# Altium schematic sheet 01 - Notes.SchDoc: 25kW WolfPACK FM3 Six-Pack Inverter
size 431 x 279 mm; Date: 09/2024; DocumentNumber: CRD25DA12N-FMC; Revision: 2.0; SheetNumber: 1; SheetTotal: 9; SheetSize: B
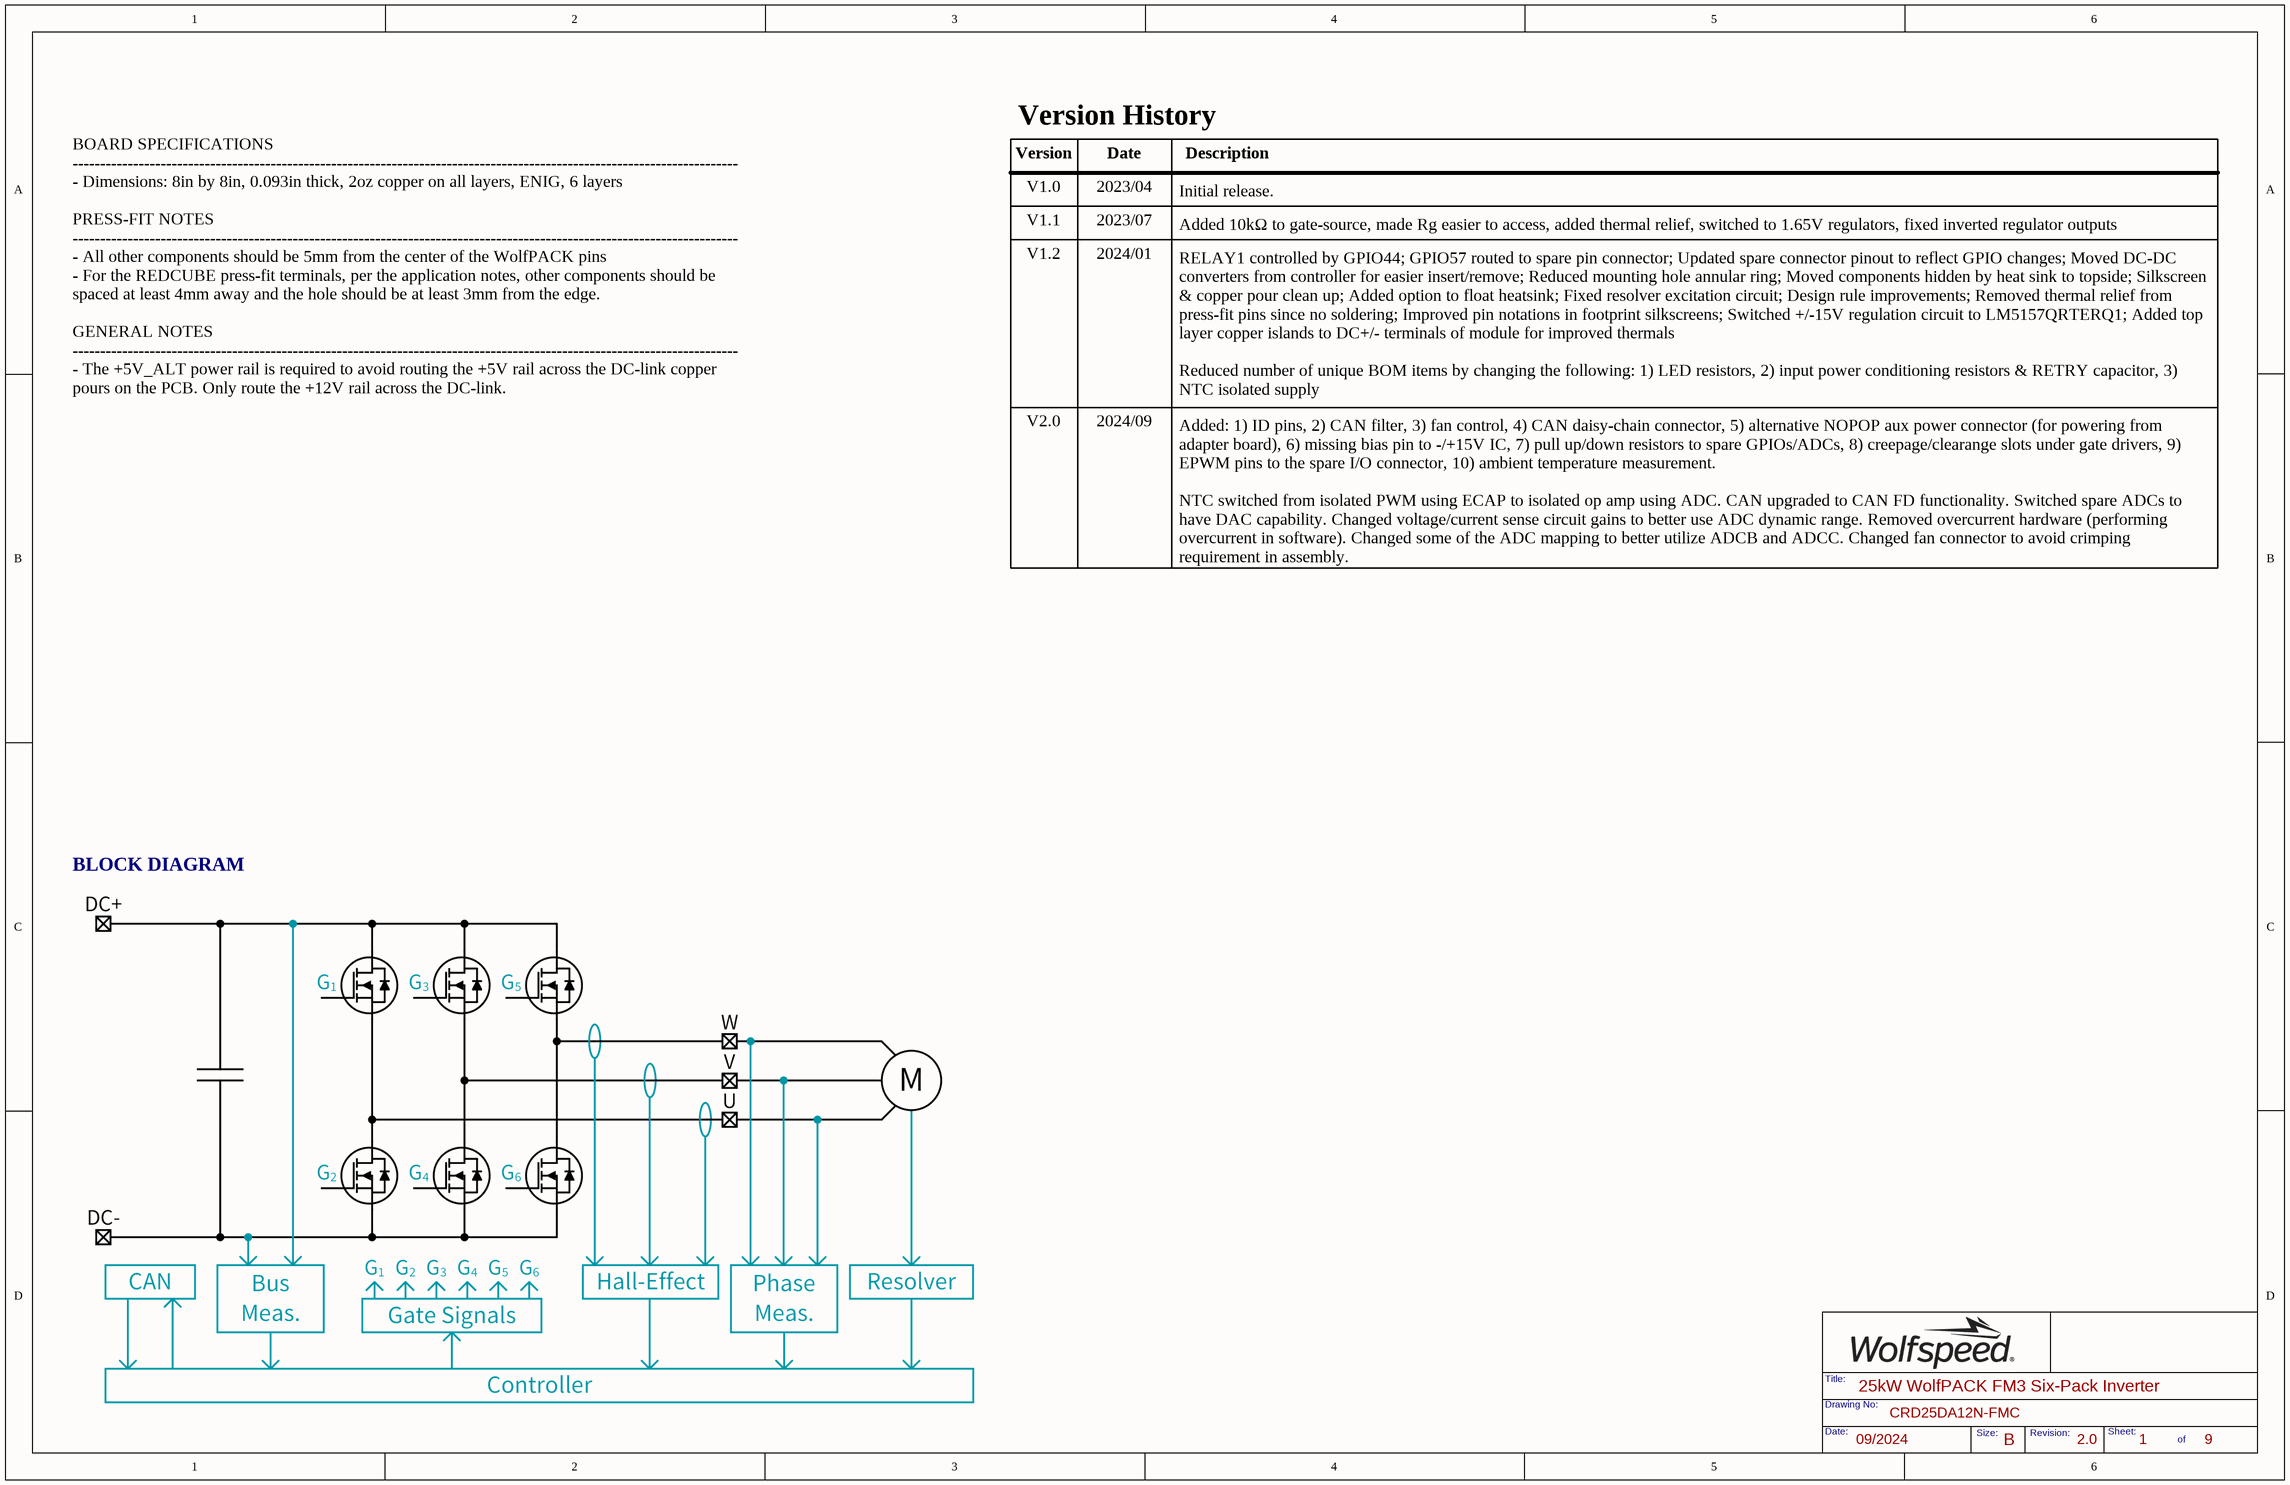
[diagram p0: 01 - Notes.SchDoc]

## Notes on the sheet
- Version History
- Version
- Date
- Description
- V1.0
- V1.1
- 2023/04
- 2023/07
- Initial release.
- Added 10kΩ to gate-source, made Rg easier to access, added thermal relief, switched to 1.65V regulators, fixed inverted regulator outputs
- V1.2
- 2024/01
- V2.0
- 2024/09
- RELAY1 controlled by GPIO44; GPIO57 routed to spare pin connector; Updated spare connector pinout to reflect GPIO changes; Moved DC-DC converters from controller for easier insert/remove; Reduced mounting hole annular ring; Moved components hidden by heat sink to topside; Silkscreen & copper pour clean up; Added option to float heatsink; Fixed resolver excitation circuit; Design rule improvements; Removed thermal relief from press-fit pins since no soldering; Improved pin notations in footprint silkscreens; Switched +/-15V regulation circuit to LM5157QRTERQ1; Added top layer copper islands to DC+/- terminals of module for improved thermals
  Reduced number of unique BOM items by changing the following: 1) LED resistors, 2) input power conditioning resistors & RETRY capacitor, 3) NTC isolated supply
- BOARD SPECIFICATIONS
  -------------------------------------------------------------------------------------------------------------------------
  - Dimensions: 8in by 8in, 0.093in thick, 2oz copper on all layers, ENIG, 6 layers
  PRESS-FIT NOTES
  -------------------------------------------------------------------------------------------------------------------------
  - All other components should be 5mm from the center of the WolfPACK pins
  - For the REDCUBE press-fit terminals, per the application notes, other components should be spaced at least 4mm away and the hole should be at least 3mm from the edge.
  GENERAL NOTES
  -------------------------------------------------------------------------------------------------------------------------
  - The +5V_ALT power rail is required to avoid routing the +5V rail across the DC-link copper pours on the PCB. Only route the +12V rail across the DC-link.
- Added: 1) ID pins, 2) CAN filter, 3) fan control, 4) CAN daisy-chain connector, 5) alternative NOPOP aux power connector (for powering from adapter board), 6) missing bias pin to -/+15V IC, 7) pull up/down resistors to spare GPIOs/ADCs, 8) creepage/clearange slots under gate drivers, 9) EPWM pins to the spare I/O connector, 10) ambient temperature measurement.
  NTC switched from isolated PWM using ECAP to isolated op amp using ADC. CAN upgraded to CAN FD functionality. Switched spare ADCs to have DAC capability. Changed voltage/current sense circuit gains to better use ADC dynamic range. Removed overcurrent hardware (performing overcurrent in software). Changed some of the ADC mapping to better utilize ADCB and ADCC. Changed fan connector to avoid crimping requirement in assembly.
- BLOCK DIAGRAM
